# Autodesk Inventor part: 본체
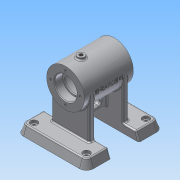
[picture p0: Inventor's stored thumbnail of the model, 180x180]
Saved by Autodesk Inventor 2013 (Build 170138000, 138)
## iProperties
Created: 2016-07
Part Number: 본체
Material: 알루미늄 6061
Document SubType Name: Modeling
Designer: mrc
Density: 2.71 g/cm^3
Mass: 499.419 g
Surface Area: 540.243 cm^2
Volume: 184.287 cm^3
Author: mrc
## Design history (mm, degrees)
sketch "스케치1"
  geometry: L1 (-35, 0)-(-35, 16); L2 (-35, 27)-(35, 27); L3 (35, 27)-(35, 17); L4 (35, 0)-(-35, 0); L5 (-34, 16)-(-23, 16); L6 (-23, 16)-(-23, 14); L7 (-23, 14)-(-21, 14); L8 (-21, 14)-(-21, 19); L9 (-18, 22)-(18, 22); L10 (21, 19)-(21, 14); L11 (21, 14)-(23, 14); L12 (23, 14)-(23, 16); L13 (23, 16)-(34, 16); L14 (-35, 17)-(-35, 27); L15 (35, 16)-(35, 0); L16 (-34, 16)-(-35, 17); L17 (34, 16)-(35, 17); A1 r 3 centre (-18, 19) between (-18, 22) and (-21, 19); A2 r 3 centre (18, 19) between (21, 19) and (18, 22); 3 further points
  constraints: 34 end point, 12 parallel, 5 perpendicular, 4 point on circle, 4 point on line, 4 tangent, 2 centre point, 2 midpoint, 2 vertical, 1 coincident, 1 equal radius, 1 vertical alignment
  dimensions: "d0" = 54 diameter of L2 L4; "d2" = 32 diameter of L13 L4; "d3" = 28 diameter of L11 L4; "d4" = 44 diameter of L9 L4; "d5" = 32 diameter of L5 L4; "d6" = 28 diameter of L7 L4; "d7" = 70 distance between parallel lines of L3 L1; "d8" = 12 distance between parallel lines of L3 L12; "d9" = 42 distance between parallel lines of L10 L8; "d10" = 12 distance between parallel lines of L1 L6; "d11" = 1 distance of L5.start L1.end; "d12" = 45 deg angle of L5 L16; "d13" = 1 distance of L13.end L15.start (= d11); "d14" = 45 deg angle of L13 L17 (= d12); "d15" = 3 radius of A1
revolve "회전1" sketch "스케치1" stored, may be unused: angle "d16" = 90 deg
node "작업 평면2"
  node "작업 평면1"
sketch "스케치2"
  geometry: L1 (-35, 27)-(-35, -27) reference; L2 (35, 27)-(35, -27) reference; C1 r 5 at (13, 0); 1 further point
  constraints: 1 centre point, 1 horizontal alignment
  dimensions: "d18" = 10 diameter of C1; "d19" = 22 distance from line of L2 C1.centre
extrude "돌출1" join sketch "스케치2" stored distance "d20" = 10; taper "d21" = 0 deg
hole "구멍1" diameter "d24" = 5.188; stored, may be unused: countersink angle "d28" = 90 deg, drill point angle "d30" = 0 deg; dims "d22" = 10, "d23" = 10, "d25" = 6, "d26" = 4, "d27" = 2, "d29" = 8
node "작업 평면4"
  node "작업 평면3"
sketch "스케치4"
  geometry: C1 r 27 at (0, 0) reference; 1 further point
  constraints: 1 vertical alignment
  dimensions: "d45" = 21 distance of C1.centre point (0, 21)
hole "구멍3" sketch "스케치4" at (0, 21) diameter "d46" = 3.242; stored, may be unused: countersink angle "d50" = 90 deg, drill point angle "d52" = 118 deg; dims "d47" = 8, "d48" = 4, "d49" = 2, "d51" = 10
fillet "모깎기1" dims "d56" = 2
node "작업 평면5"
sketch "스케치5"
  geometry: L1 (-45, -50)-(-20, -50); L2 (55, -40)-(55, 40); L3 (45, 50)-(20, 50); L4 (-55, 40)-(-55, -40); L5 (-55, -50)-(55, 50); L6 (55, -50)-(-55, 50); L7 (-20, -50)-(-20, 50); L8 (20, -50)-(20, 50); L9 (-20, -50)-(20, -50); L10 (20, -50)-(45, -50); L11 (-20, 50)-(-45, 50); L12 (20, 50)-(-20, 50); L13 (-55, 0)-(55, 0); A1 r 10 centre (-45, -40) between (-55, -40) and (-45, -50); A2 r 10 centre (-45, 40) between (-45, 50) and (-55, 40); A3 r 10 centre (45, 40) between (55, 40) and (45, 50); A4 r 10 centre (45, -40) between (45, -50) and (55, -40); 5 further points
  constraints: 26 end point, 10 parallel, 9 perpendicular, 9 point on line, 8 point on circle, 8 tangent, 7 midpoint, 4 centre point, 3 equal radius, 3 horizontal, 1 coincident
  dimensions: "d58" = 110 distance of L6.end L5.end; "d59" = 100 distance of L5.end L6.start; "d60" = 35 distance between parallel lines of L7 L4; "d61" = 35 distance between parallel lines of L2 L8; "d66" = 10 radius of A1
extrude "돌출3" join sketch "스케치5" distance "d67" = 12; taper "d68" = 0 deg
extrude "돌출4" cut sketch "스케치5" distance "d69" = 12; taper "d70" = 0 deg
sketch "스케치6"
  geometry: L1 (-20, -50)-(-20, 50) reference; L2 (-45, -50)-(-20, -50) reference; L3 (-28, 27)-(-28, -27); L4 (-28, -27)-(-20, -27); L5 (-28, 27)-(-20, 27); L6 (20, -50)-(20, 50) reference; L7 (20, 27)-(28, 27); L8 (28, 27)-(28, -27); L9 (28, -27)-(20, -27); 3 further points
  constraints: 12 end point, 6 perpendicular, 4 point on line, 2 horizontal alignment, 2 midpoint
  dimensions: "d71" = 8 distance between parallel lines of L1 L3; "d72" = 54 distance between parallel lines of L4 L5; "d73" = 8 distance between parallel lines of L6 L8; "d74" = 54 distance between parallel lines of L9 L7
extrude "돌출5" join sketch "스케치6" stored distance "d75" = 12; taper "d76" = 0 deg
sketch "스케치7"
  geometry: L1 (18, 22)-(-10.406, 22) reference; L2 (-10.406, 22)-(-10.406, 30) reference; L3 (-10.406, 30)-(-8, 30) reference; L4 (-8, 30)-(-8, 29) reference; L5 (-6, 27)-(35, 27) reference; L6 (35, 27)-(35, 22.621) reference; L7 (35, 22.621)-(25, 22.621) reference; L8 (25, 22.621)-(24.026, 21) reference; L9 (24.026, 21)-(25, 19.379) reference; L10 (25, 19.379)-(35, 19.379) reference; L11 (35, 19.379)-(35, 17) reference; L12 (35, 17)-(34, 16) reference; L13 (34, 16)-(23, 16) reference; L14 (23, 16)-(23, 14) reference; L15 (23, 14)-(21, 14) reference; L16 (21, 14)-(21, 19) reference; L17 (-15.594, 22)-(-18, 22) reference; L18 (-21, 19)-(-21, 14) reference; L19 (-21, 14)-(-23, 14) reference; L20 (-23, 14)-(-23, 16) reference; L21 (-23, 16)-(-34, 16) reference; L22 (-34, 16)-(-35, 17) reference; L23 (-35, 17)-(-35, 19.379) reference; L24 (-35, 19.379)-(-25, 19.379) reference; L25 (-25, 19.379)-(-24.026, 21) reference; L26 (-24.026, 21)-(-25, 22.621) reference; L27 (-25, 22.621)-(-35, 22.621) reference; L28 (-35, 22.621)-(-35, 27) reference; L29 (-35, 27)-(-20, 27) reference; L30 (-18, 29)-(-18, 30) reference; L31 (-18, 30)-(-15.594, 30) reference; L32 (-15.594, 30)-(-15.594, 22) reference; L33 (-18, -22)-(18, -22) reference; L34 (21, -19)-(21, -14) reference; L35 (21, -14)-(23, -14) reference; L36 (23, -14)-(23, -16) reference; L37 (23, -16)-(34, -16) reference; L38 (34, -16)-(35, -17) reference; L39 (35, -17)-(35, -19.379) reference; L40 (35, -19.379)-(25, -19.379) reference; L41 (25, -19.379)-(24.026, -21) reference; L42 (24.026, -21)-(25, -22.621) reference; L43 (25, -22.621)-(35, -22.621) reference; L44 (35, -22.621)-(35, -27) reference; L45 (35, -27)-(28, -27) reference; L46 (28, -27)-(28, -58) reference; L47 (28, -58)-(55, -58) reference; L48 (55, -58)-(55, -70) reference; L49 (55, -70)-(20, -70) reference; L50 (20, -70)-(20, -27) reference; L51 (20, -27)-(-20, -27) reference; L52 (-20, -27)-(-20, -70) reference; L53 (-20, -70)-(-55, -70) reference; L54 (-55, -70)-(-55, -58) reference; L55 (-55, -58)-(-28, -58) reference; L56 (-28, -58)-(-28, -27) reference; L57 (-28, -27)-(-35, -27) reference; L58 (-35, -27)-(-35, -22.621) reference; L59 (-35, -22.621)-(-25, -22.621) reference; L60 (-25, -22.621)-(-24.026, -21) reference; L61 (-24.026, -21)-(-25, -19.379) reference; L62 (-25, -19.379)-(-35, -19.379) reference; L63 (-35, -19.379)-(-35, -17) reference; L64 (-35, -17)-(-34, -16) reference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; A1 r 3 centre (18, 19) between (21, 19) and (18, 22) reference; A2 r 3 centre (-18, 19) between (-18, 22) and (-21, 19) reference; A3 r 3 centre (18, -19) between (18, -22) and (21, -19) reference; A4 r 3 centre (-18, -19) between (-21, -19) and (-18, -22) reference; A5 r 3.5 centre (8, -38) between (8, -41.5) and (8, -34.5); A6 r 3.5 centre (-8, -38) between (-8, -34.5) and (-8, -41.5); 2 further points
  constraints: 6 end point, 4 point on circle, 4 tangent, 2 centre point, 2 parallel, 2 point on line, 1 midpoint, 1 perpendicular, 1 vertical alignment, 2 other
  dimensions: "d77" = 21 distance between parallel lines of L69 L51; "d78" = 23 dimension on A5 A6; "d79" = 3.5 radius of A5; "d80" = 32 distance from line of L49 A5.centre
  node "절단 모서리 투영1"
feature "리브1" dims "d81" = 1, "d82" = 8, "d83" = 0, "d84" = 0, "d85" = 1, "d86" = 1
extrude "돌출6" cut sketch "스케치7" stored distance "d87" = 50; taper "d88" = 0 deg
sketch "스케치8"
  geometry: L1 (20, -50)-(20, 50) reference; L2 (20, 50)-(45, 50) reference; L3 (55, 40)-(55, -40) reference; L4 (45, -50)-(20, -50) reference; L5 (-45, 50)-(-20, 50) reference; L6 (-20, 50)-(-20, -50) reference; L7 (-20, -50)-(-45, -50) reference; L8 (-55, -40)-(-55, 40) reference; L9 (-42.5, 37.5)-(42.5, 37.5); L10 (42.5, 37.5)-(42.5, -37.5); L11 (42.5, -37.5)-(-42.5, -37.5); L12 (-42.5, -37.5)-(-42.5, 37.5); L13 (-42.5, 37.5)-(42.5, -37.5); L14 (42.5, 37.5)-(-42.5, -37.5); A1 r 10 centre (45, 40) between (55, 40) and (45, 50) reference; A2 r 10 centre (45, -40) between (45, -50) and (55, -40) reference; A3 r 10 centre (-45, -40) between (-55, -40) and (-45, -50) reference; A4 r 10 centre (-45, 40) between (-45, 50) and (-55, 40) reference; 5 further points
  constraints: 12 end point, 4 coincident, 2 midpoint, 2 parallel, 1 horizontal, 1 perpendicular
  dimensions: "d89" = 85 distance of L10.end L11.end; "d90" = 75 distance of L9.end L10.end
hole "구멍4" sketch "스케치8" at (-42.5, 37.5), (-42.5, -37.5), (42.5, -37.5), (42.5, 37.5) diameter "d91" = 6; stored, may be unused: countersink angle "d95" = 90 deg, drill point angle "d97" = 0 deg; dims "d92" = 8, "d93" = 4, "d94" = 2, "d96" = 12
hole "구멍5" diameter "d100" = 10; stored, may be unused: countersink angle "d104" = 90 deg, drill point angle "d106" = 0 deg; dims "d98" = 10, "d99" = 10, "d101" = 8, "d102" = 4, "d103" = 2, "d105" = 4
hole "구멍6" diameter "d109" = 10; stored, may be unused: countersink angle "d113" = 90 deg, drill point angle "d115" = 0 deg; dims "d107" = 10, "d108" = 10, "d110" = 8, "d111" = 4, "d112" = 2, "d114" = 4
hole "구멍7" diameter "d118" = 10; stored, may be unused: countersink angle "d122" = 90 deg, drill point angle "d124" = 0 deg; dims "d116" = 10, "d117" = 10, "d119" = 8, "d120" = 4, "d121" = 2, "d123" = 4
hole "구멍8" diameter "d127" = 10; stored, may be unused: countersink angle "d131" = 90 deg, drill point angle "d133" = 0 deg; dims "d125" = 10, "d126" = 10, "d128" = 8, "d129" = 4, "d130" = 2, "d132" = 4
fillet "모깎기2" dims "d134" = 2
feature "면 기울기1" dims angle "d135" = 20 deg
sketch "스케치9"
  geometry: L1 (26, 29)-(20, 29) reference; L2 (30, -25)-(30, 25) reference; L3 (20, -29)-(26, -29) reference; L4 (20, -29)-(20, -45.632) reference; L5 (20, -45.632)-(45, -45.632) reference; L6 (50.632, -40)-(50.632, 40) reference; L7 (45, 45.632)-(20, 45.632) reference; L8 (20, 45.632)-(20, 29) reference; C1 r 5 at (42.5, -37.5) reference; C2 r 5 at (42.5, 37.5) reference; A1 r 4 centre (26, 25) between (30, 25) and (26, 29) reference; A2 r 4 centre (26, -25) between (26, -29) and (30, -25) reference; A3 r 5.632 centre (45, -40) between (45, -45.632) and (50.632, -40) reference; A4 r 5.632 centre (45, 40) between (50.632, 40) and (45, 45.632) reference; 1 further point
feature "면 기울기2" dims angle "d136" = 20 deg
fillet "모깎기3" dims "d137" = 2
fillet "모깎기4" dims "d138" = 2
fillet "모깎기5" dims "d139" = 2
fillet "모깎기6" dims "d140" = 2
fillet "모깎기7" dims "d141" = 2
node "작업 평면6"
sketch "스케치10"
  geometry: L1 (-35, 27)-(35, 27) reference; 2 further points
  constraints: 1 coincident, 1 other
feature "엠보싱1" sketch "스케치10" dims "d0" = 54, "d2" = 32, "d3" = 28, "d4" = 44, "d5" = 32, "d6" = 28, "d7" = 70, "d8" = 12, "d9" = 42, "d10" = 12, "d11" = 1, "d12" = 45 deg, "d13" = 1 (= d11), "d14" = 45 deg (= d12), "d15" = 3, "d142" = 0.5, "d143" = 0
node "작업 평면8"
  node "작업 평면7"
sketch "스케치11"
  geometry: C1 r 6 at (0, 0); 1 further point
  constraints: 1 centre point, 1 coincident
  dimensions: "d146" = 12 diameter of C1
extrude "돌출7" join sketch "스케치11" stored distance "d147" = 50; taper "d148" = 0 deg
hole "구멍9" diameter "d151" = 5.188; stored, may be unused: countersink angle "d155" = 90 deg, drill point angle "d157" = 0 deg; dims "d149" = 10, "d150" = 10, "d152" = 8, "d153" = 4, "d154" = 2, "d156" = 4
fillet "모깎기8" dims "d158" = 2
fillet "모깎기9" dims "d159" = 0.3
fillet "모깎기10" dims "d160" = 0.3
fillet "모깎기11" dims "d161" = 2
node "솔리드1"
pattern_circular "원형 패턴1" dims angle "d54" = 360 deg
mirror "대칭1"
node "투영된 루프1"
node "절단 모서리 투영2"
other parameters: "d17" = 3, "d31" = 58 deg, "d144" = -58 deg
